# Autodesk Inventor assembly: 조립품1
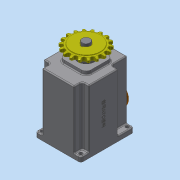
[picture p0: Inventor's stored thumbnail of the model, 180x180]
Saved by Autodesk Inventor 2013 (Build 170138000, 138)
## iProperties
Created: 2017-12
Part Number: 조립품1
Document SubType Name: Assembly
Designer: dgall
Mass: 2741.19 g
Surface Area: 2015.58 cm^2
Volume: 734.131 cm^3
Density: 3.73392 g/cm^3
Author: dgall
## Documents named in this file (17)
- C:\Users\dgall\Desktop\371207V1017\조립품1.iam
- C:\Users\dgall\Desktop\371207V1017\본체.ipt
- C:\Users\dgall\Desktop\371207V1017\오일 실 8 22 7.ipt
- C:\Users\dgall\Desktop\371207V1017\커버.ipt
- C:\Users\dgall\Desktop\371207V1017\베어링 608.ipt
- C:\Users\dgall\Desktop\371207V1017\볼트 M4 x 10.ipt
- C:\Users\dgall\Desktop\371207V1017\메인축.ipt
- C:\Users\dgall\Desktop\371207V1017\서브축.ipt
- C:\Users\dgall\Desktop\371207V1017\베어링 6003.ipt
- C:\Users\dgall\Desktop\371207V1017\키 5 x 5 x 18.ipt
- C:\Users\dgall\Desktop\371207V1017\오일 실 17 32 8.ipt
- C:\Users\dgall\Desktop\371207V1017\스프로킷.ipt
- C:\Users\dgall\Desktop\371207V1017\멈춤나사 M3x8.ipt
- C:\Users\dgall\Desktop\371207V1017\상부 캡.ipt
- C:\Users\dgall\Desktop\371207V1017\슬라이더.ipt
- C:\Users\dgall\Desktop\371207V1017\가변스프링.ipt
- C:\Users\dgall\Desktop\371207V1017\부시.ipt
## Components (1 placed, 1 different names)
1. 가변스프링:1
